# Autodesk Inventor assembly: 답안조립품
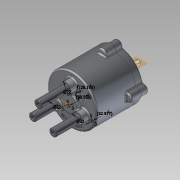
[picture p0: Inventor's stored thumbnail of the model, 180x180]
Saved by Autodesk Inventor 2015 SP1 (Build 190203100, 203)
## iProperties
Created: 2014-12
Part Number: 답안조립품
Document SubType Name: Assembly
Designer: mypark
Mass: 2107.58 g
Surface Area: 1801.23 cm^2
Volume: 438.526 cm^3
Density: 4.80606 g/cm^3
Author: mypark
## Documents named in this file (14)
- C:\Users\mypark\Desktop\Inventor1급-박미영\답안조립품.iam
- C:\Users\mypark\Desktop\Inventor1급-박미영\몸체.ipt
- C:\Users\mypark\Desktop\Inventor1급-박미영\M5x0.5x20.ipt
- C:\Users\mypark\Desktop\Inventor1급-박미영\가변 스프링-01.ipt
- C:\Users\mypark\Desktop\Inventor1급-박미영\가변 스프링-02.ipt
- C:\Users\mypark\Desktop\Inventor1급-박미영\가변 스프링-03.ipt
- C:\Users\mypark\Desktop\Inventor1급-박미영\멈춤링 10 x 1.ipt
- C:\Users\mypark\Desktop\Inventor1급-박미영\멈춤링 22 x 1.2.ipt
- C:\Users\mypark\Desktop\Inventor1급-박미영\메인 축.ipt
- C:\Users\mypark\Desktop\Inventor1급-박미영\베어링 NA 4900.ipt
- C:\Users\mypark\Desktop\Inventor1급-박미영\슬라이드 축.ipt
- C:\Users\mypark\Desktop\Inventor1급-박미영\오일실.ipt
- C:\Users\mypark\Desktop\Inventor1급-박미영\커버.ipt
- C:\Users\mypark\Desktop\Inventor1급-박미영\판캠.ipt
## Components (7 placed, 4 different names)
1. M5x0.5x20:1
2. 가변 스프링-01:1
3. 가변 스프링-02:1
4. 가변 스프링-03:1
5. M5x0.5x20:2
6. M5x0.5x20:3
7. M5x0.5x20:4
